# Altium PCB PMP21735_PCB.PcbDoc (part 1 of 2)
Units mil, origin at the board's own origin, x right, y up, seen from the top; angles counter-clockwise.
Board outline 1970 x 1570 mil, 4 copper layers (Top Layer, Signal Layer 1, Signal Layer 2, Bottom Layer), stack 61.6 mil thick; 74 components, 39 nets, 158 pads, 32 vias.
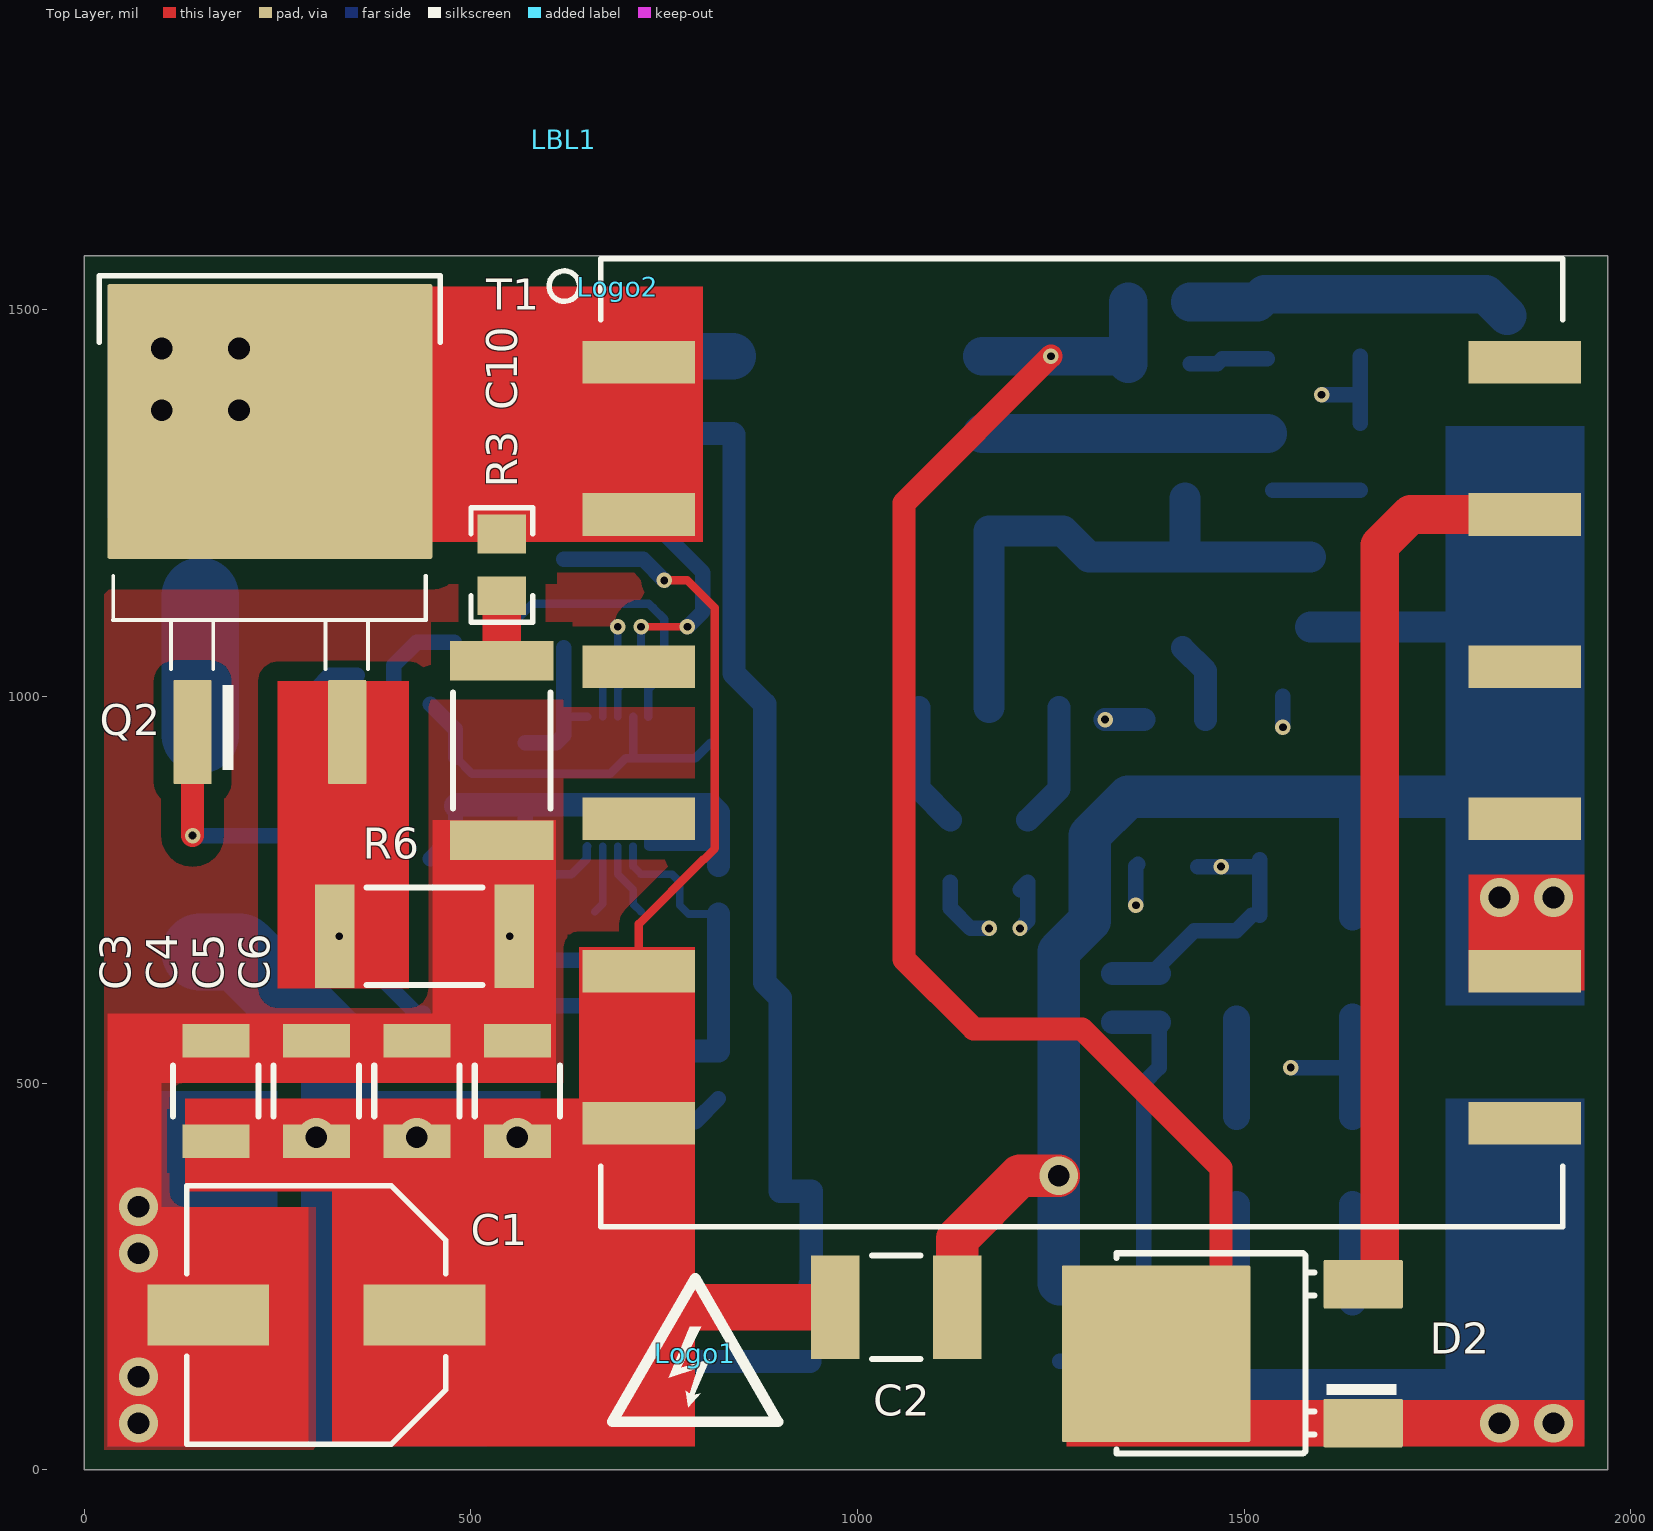
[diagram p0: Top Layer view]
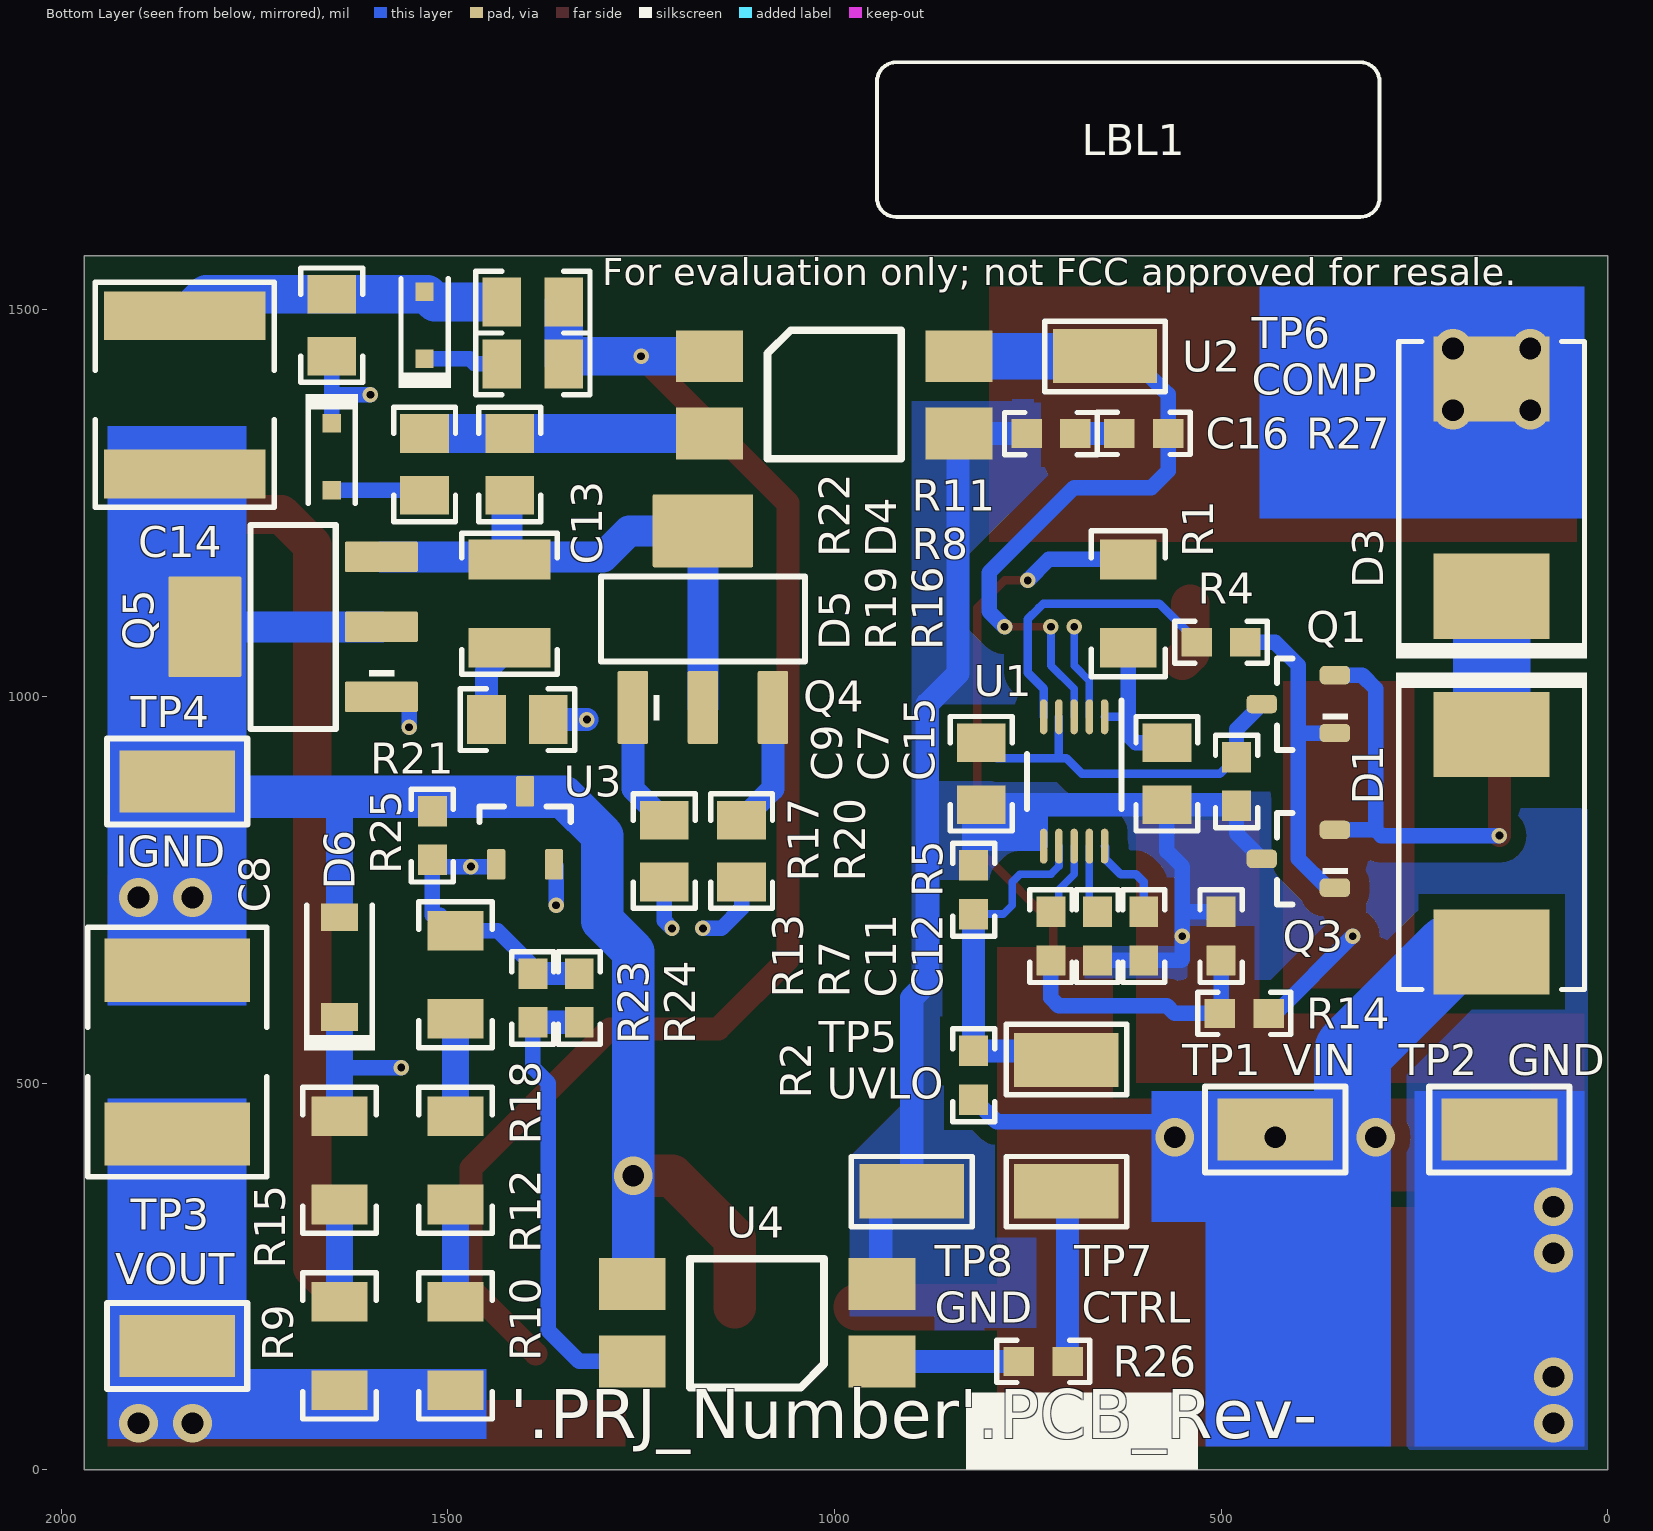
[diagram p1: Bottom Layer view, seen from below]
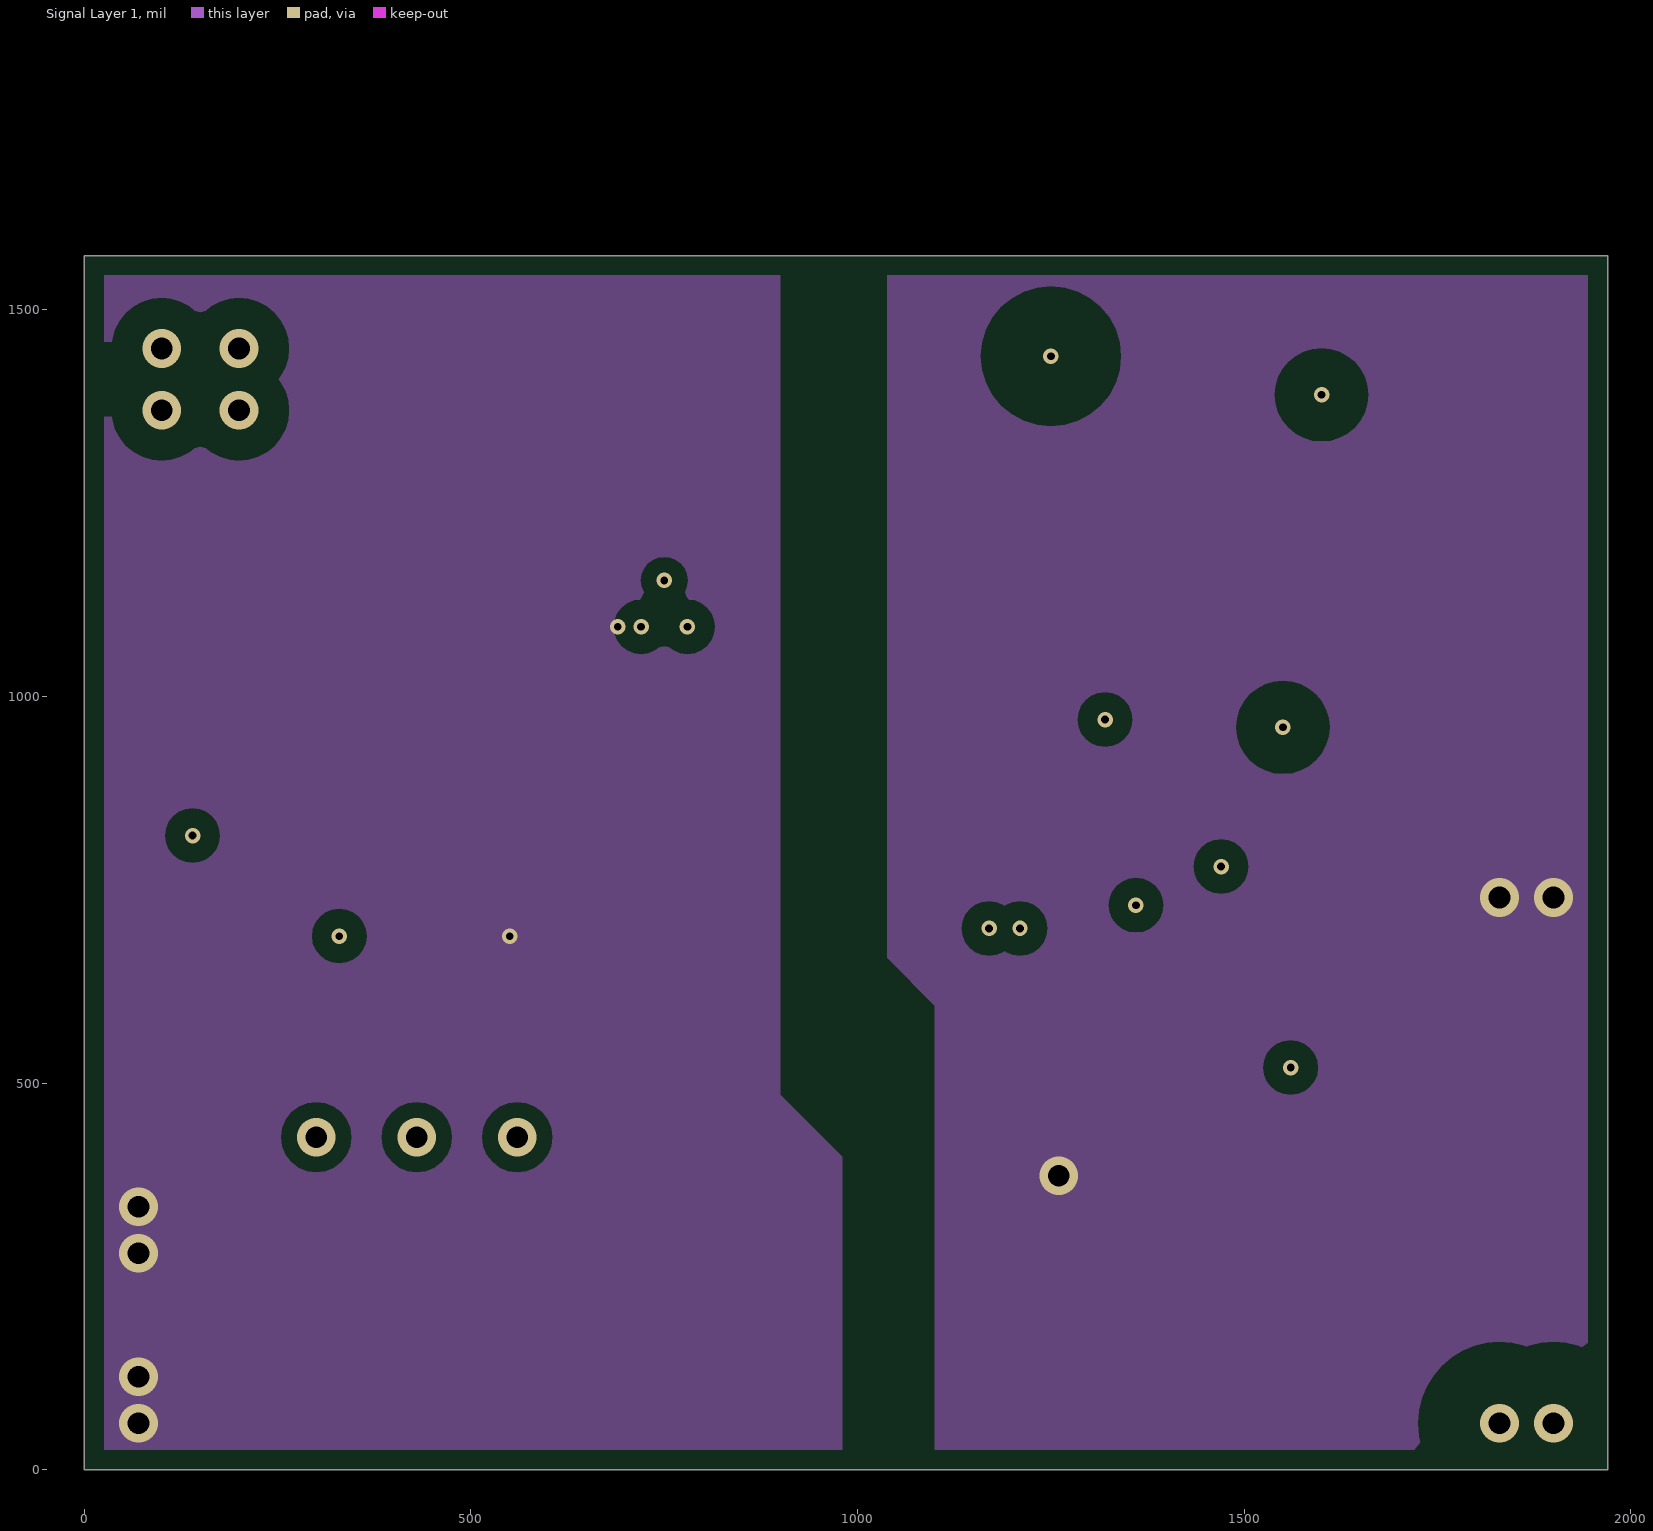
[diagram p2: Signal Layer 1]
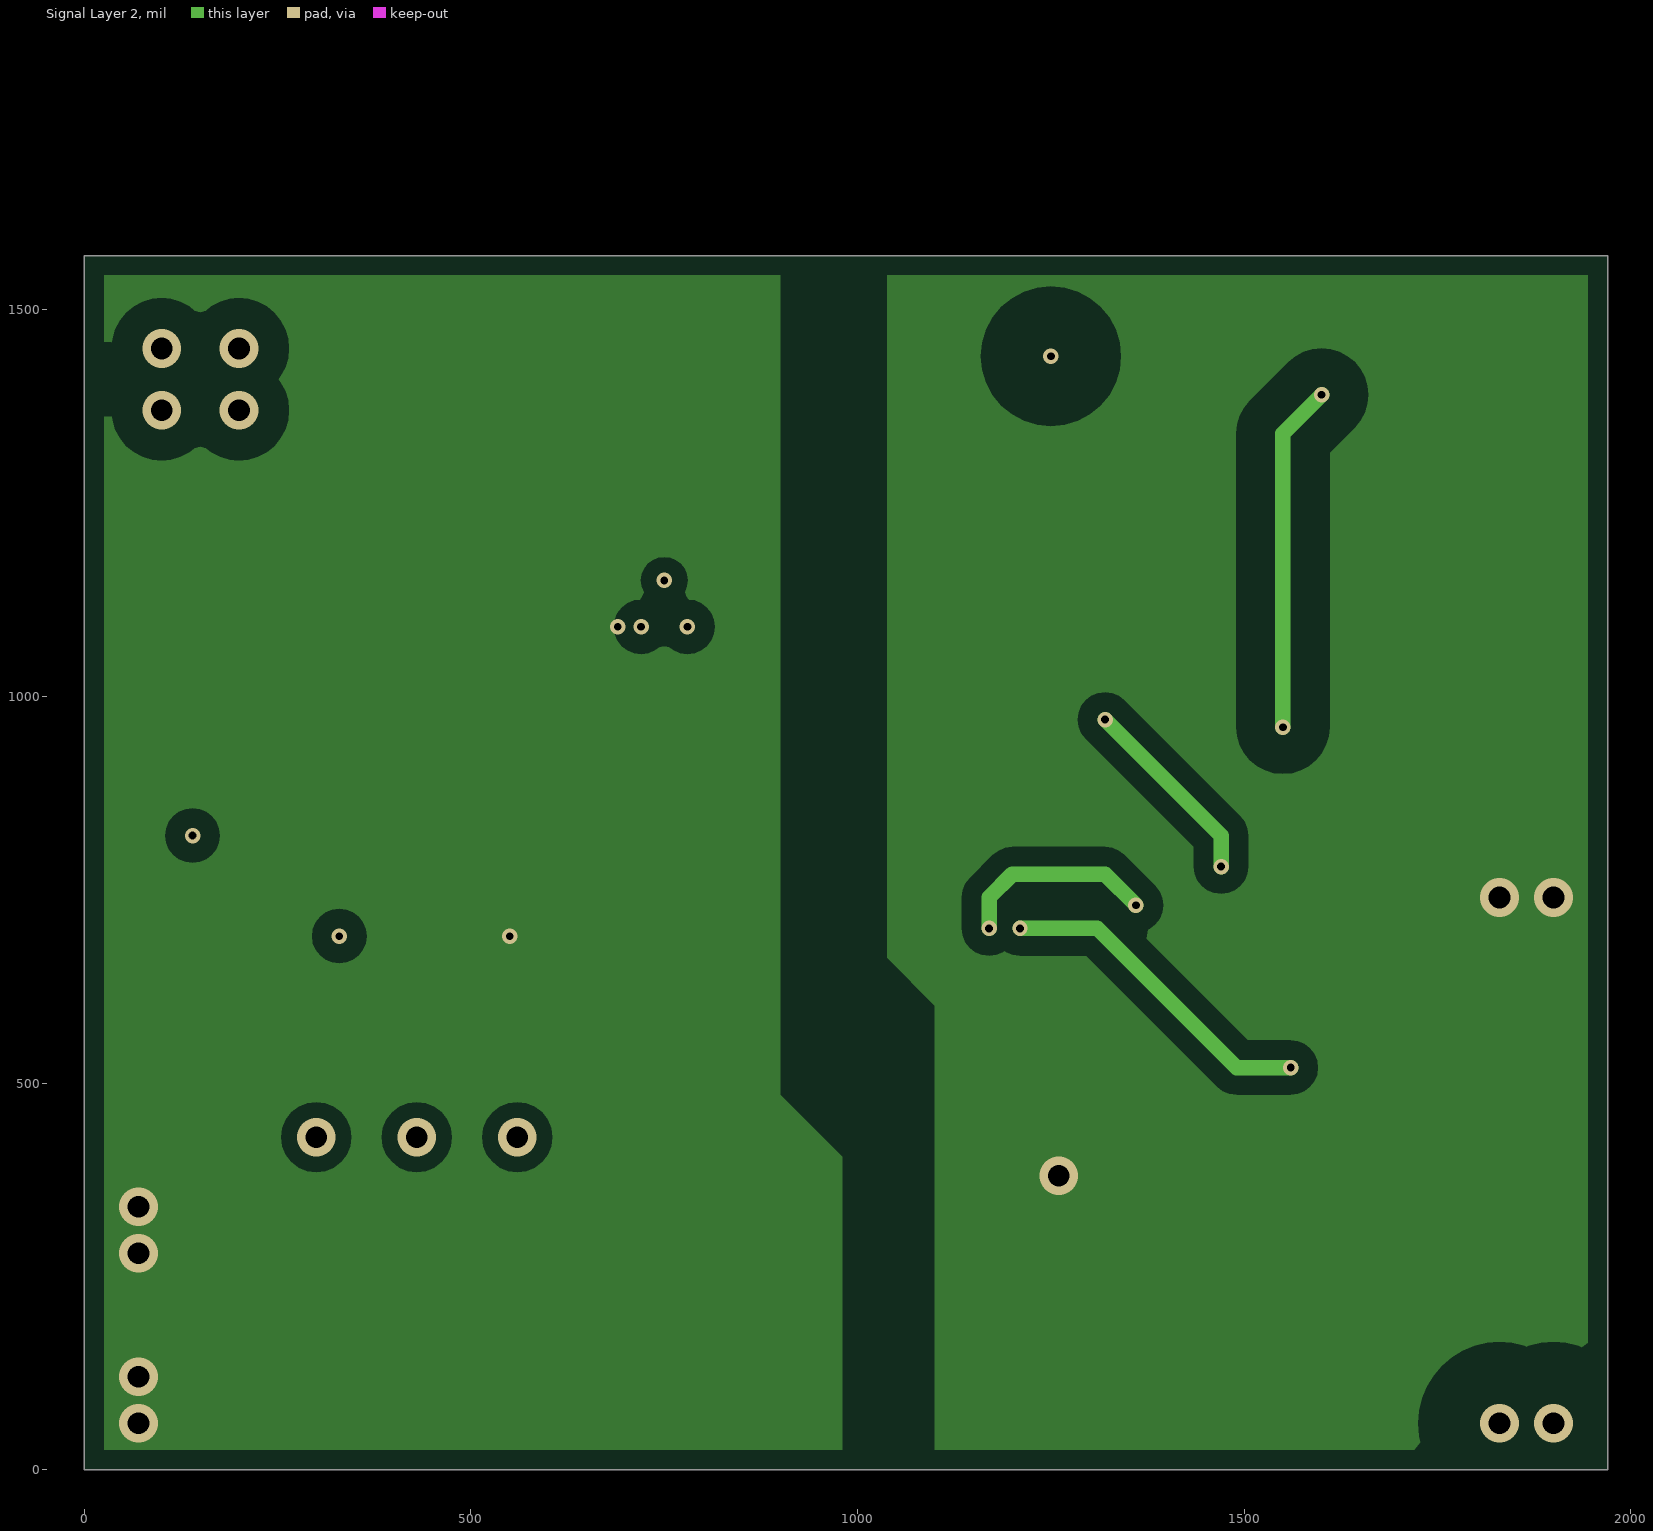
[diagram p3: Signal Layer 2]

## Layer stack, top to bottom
Top Solder: solder mask 0.4, Solder Resist, Dk 3.5
Top Layer: signal copper 1.4
Dielectric 1: prepreg 8, FR-4, Dk 4.2
Signal Layer 1: signal copper 1.4
Dielectric 2: core 40, FR-4, Dk 4.2
Signal Layer 2: signal copper 1.4
Dielectric 3: prepreg 8, FR-4, Dk 4.2
Bottom Layer: signal copper 1.4
Bottom Solder: solder mask 0.4, Solder Resist, Dk 3.5

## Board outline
0,0 1970,0 1970,1570 0,1570

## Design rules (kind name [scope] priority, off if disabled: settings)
AcuteAngle [All] p1: minimum=4.50000000000000E+0001 checktracksonly=FALSE
AssemblyTestPointUsage [All] p1: valid=2
BoardOutlineClearance BoardOutlineClearance_MountingHoles [OnCopper and InComponentClass('Mounting Holes')] p1: gap=40 ignorepadtopadclearanceinfootprint=FALSE
BoardOutlineClearance BoardOutlineClearance_Poly [OnCopper and IsPoly] p2: gap=25 ignorepadtopadclearanceinfootprint=FALSE
BoardOutlineClearance [OnCopper and Not InComponentClass('Logo') and not InComponentClass('FiducialMark') and not InRegion(1000,500,4000,800) and not InPoly] p3: gap=25 ignorepadtopadclearanceinfootprint=FALSE
Clearance Clearance_VIN_NoNet [InNet('VIN') vs InNet('No Net')] p1: gap=10 ignorepadtopadclearanceinfootprint=TRUE
Clearance Clearance_VIN_BP [InNet('VIN') vs InNet('BP')] p2: gap=8 ignorepadtopadclearanceinfootprint=TRUE
Clearance Clearance_VOUT_FB [InNet('VOUT') vs (InNet('FBT') OR InNet('RBT') OR InNet('VBZ'))] p3: gap=60 ignorepadtopadclearanceinfootprint=FALSE
Clearance Clearance_VOUT_SEC [InNet('VOUT') vs (InNet('SECSS') OR InNet('VK') OR InNet('VDK'))] p4: gap=20 ignorepadtopadclearanceinfootprint=FALSE
Clearance Clearance_VBP_VK [InNet('VBP') vs (InNet('VK') OR InNet('SECSS') OR InNet('VDK') OR InNet('VDA'))] p5: gap=20 ignorepadtopadclearanceinfootprint=FALSE
Clearance Clearance_VBP [InNet('VBP')] p6: gap=50 ignorepadtopadclearanceinfootprint=FALSE
Clearance Clearance_SWS [InNet('SWS')] p7: gap=80 ignorepadtopadclearanceinfootprint=TRUE
Clearance Clearance_VOUT [InNet('VOUT')] p8: gap=80 ignorepadtopadclearanceinfootprint=TRUE
Clearance Clearance_SWZ [InNet('SWZ')] p9: gap=40 ignorepadtopadclearanceinfootprint=TRUE
Clearance Clearance_SWP [InNet('SWP')] p10: gap=40 ignorepadtopadclearanceinfootprint=TRUE
Clearance Clearance_VIN [InNet('VIN')] p11: gap=20 ignorepadtopadclearanceinfootprint=TRUE
Clearance Clearance_Keepouts [((IsTrack Or IsArc) And Not InPoly) And IsFree and IsKeepOut vs ((IsTrack Or IsArc) And Not InPoly) And IsFree and IsKeepOut] p12: gap=0 ignorepadtopadclearanceinfootprint=FALSE
Clearance Clearance_Poly [InPolygon] p13: gap=25 ignorepadtopadclearanceinfootprint=FALSE except(0: Arc-Hole Track-Hole SMDPad-Hole THPad-Hole Via-Hole Fill-Hole Poly-Hole Region-Hole Text-Hole)
Clearance Clearance_FiducialMark [IsKeepOut and InComponentClass('FiducialMark') vs IsPad and InComponentClass('FiducialMark')] p14: gap=0 ignorepadtopadclearanceinfootprint=FALSE
Clearance [All] p15: gap=7.87 ignorepadtopadclearanceinfootprint=FALSE except(0: Arc-Hole Track-Hole SMDPad-Hole THPad-Hole Via-Hole Fill-Hole Poly-Hole Region-Hole Text-Hole)
ComponentClearance ComponentClearance_MountingHoles_FiducialMarks [InComponentClass('Mounting Holes') vs InComponentClass('FiducialMark')] p1: gap=50 collisioncheckmode=3 verticalgap=10 showdistances=FALSE
ComponentClearance ComponentClearance_Shunt [InComponentClass('Header') vs InComponentClass('Shunt')] p2: gap=0 collisioncheckmode=3 verticalgap=0 showdistances=FALSE
ComponentClearance ComponentClearance_Logo [InComponentClass('Logo')] p3: gap=50 collisioncheckmode=3 verticalgap=10 showdistances=FALSE
ComponentClearance ComponentClearance_ScrewToNut [(HasFootprint('NY PMS 440 0025 PH')) vs (HasFootprint('Keystone_1902C'))] p4: gap=5 collisioncheckmode=3 verticalgap=10 showdistances=FALSE
ComponentClearance ComponentClearance_MountingHoles [InComponentClass('Mounting Holes')] p5: gap=250 collisioncheckmode=3 verticalgap=100000 showdistances=FALSE
ComponentClearance ComponentClearance_SmallPassives [HasFootprint('0201*') or HasFootprint('0402*') or HasFootprint('0508') or HasFootprint('0603*') or HasFootprint('0612') or HasFootprint('0805*') or HasFootprint('0815*') or HasFootprint('0830*') or HasFootprint('1206*') or HasFootprint('1210*') or HasFootprint('1808*') or HasFootprint('1812*') or HasFootprint('1825*') or HasFootprint('2010*') or HasFootprint('2220*') or HasFootprint('2225*') or HasFootprint('2512*') or HasFootprint('2728*') or HasFootprint('3518*') vs HasFootprint('0201*') or HasFootprint('0402*') or HasFootprint('0508') or HasFootprint('0603*') or HasFootprint('0612') or HasFootprint('0805*') or HasFootprint('0815*') or HasFootprint('0830*') or HasFootprint('1206*') or HasFootprint('1210*') or HasFootprint('1808*') or HasFootprint('1812*') or HasFootprint('1825*') or HasFootprint('2010*') or HasFootprint('2220*') or HasFootprint('2225*') or HasFootprint('2512*') or HasFootprint('2728*') or HasFootprint('3518*')] p6: gap=14.96 collisioncheckmode=3 verticalgap=10 showdistances=FALSE
ComponentClearance ComponentClearance_THtoSMT [IsThruComponent vs IsSMTComponent] p7: gap=40 collisioncheckmode=3 verticalgap=30 showdistances=FALSE
ComponentClearance ComponentClearance_THtoTH [IsThruComponent vs IsThruComponent] p8: gap=30 collisioncheckmode=3 verticalgap=30 showdistances=FALSE
ComponentClearance [All] p9: gap=30 collisioncheckmode=3 verticalgap=10 showdistances=FALSE
DiffPairsRouting [All] p1: maxlimit=100 minlimit=10 mostfreqgap=10 toplayer_minwidth=15 toplayer_maxwidth=15 toplayer_prefwidth=15 midlayer1_minwidth=15 midlayer1_maxwidth=15 midlayer1_prefwidth=15 midlayer2_minwidth=15 midlayer2_maxwidth=15 midlayer2_prefwidth=15 bottomlayer_minwidth=15 bottomlayer_maxwidth=15 bottomlayer_prefwidth=15 maxuncoupledlength=1000
FabricationTestPointUsage TestPointUsage [All] p1: valid=2 allowmultiple=FALSE
FabricationTestpoint Testpoint [All] p1: side=3 testpointundercomponent=TRUE minsize=40 maxsize=100 preferedsize=60 minholesize=0 maxholesize=40 preferedholesize=32 testpointgrid=1 allowsidetop=TRUE allowsidebottom=TRUE usegrid=TRUE gridtolerance=0.01
FanoutControl Fanout_LCC [IsLCC] p1: bgadir=Out bgaviamode=Centered fanoutstyle=Auto fanoutdirection=Alternating viagrid=1 // Fanout_LCC (Default Rule)
FanoutControl Fanout_BGA [IsBGA] p2: bgadir=Out bgaviamode=Centered fanoutstyle=Auto fanoutdirection=Alternating viagrid=1 // Fanout_BGA (Default Rule)
FanoutControl Fanout_Default [All] p4: bgadir=Out bgaviamode=Centered fanoutstyle=Auto fanoutdirection=Alternating viagrid=1 // Fanout_Default (Default Rule)
FanoutControl Fanout_Small [(CompPinCount < 5)] p5: bgadir=Out bgaviamode=Centered fanoutstyle=Auto fanoutdirection=OutThenIn viagrid=1 // Fanout_Small (Default Rule)
HoleSize [All] p1: absolutevalues=TRUE maxlimit=251 minlimit=7.87 maxpercent=80.000 minpercent=20.000
MinimumAnnularRing MinimumAnnularRing_ThermalPadVias [IsVia and InAnyComponent] p1: minimumring=5.91
MinimumAnnularRing [All] p2: minimumring=5
MinimumSolderMaskSliver MinimumSolderMaskSliver_Logo [InComponentClass('Logo') vs InComponentClass('Logo')] p1: minsoldermaskwidth=0.7
MinimumSolderMaskSliver [All] p2: minsoldermaskwidth=3.94
PlaneConnect [All] p1: planeconnectstyle=Direct reliefexpansion=10 reliefentries=4 reliefconductorwidth=10 reliefairgap=10
PolygonConnect [All] p1: connectstyle=Direct reliefconductorwidth=10 reliefentries=4 polygonreliefangle="90 Angle" airgapwidth=10
RoutingVias ThermalPadVias [IsVia and InAnyComponent] p1: holewidth=7.87 width=19.68 viastyle="Through Hole" minholewidth=7.87 minwidth=19.68 maxholewidth=12.99 maxwidth=23.62
RoutingVias [All] p2: holewidth=16 width=34 viastyle="Through Hole" minholewidth=7.87 minwidth=20 maxholewidth=40 maxwidth=65
SilkToBoardRegionClearance [Not ((IsComment or IsDesignator) And (Hide <> 'False')) and not InRegion(1000,500,4000,800)] p1:
SilkToSilkClearance SilkToSilkClearance_Pb-FreeLogo [(HasFootprint('Pb-Free_Overlay_Medium') OR HasFootprint('Pb-Free_Overlay_Small')) vs (HasFootprint('Pb-Free_Overlay_Medium') OR HasFootprint('Pb-Free_Overlay_Small'))] p1: silktosilkclearance=0
SilkToSilkClearance [All] p2: silktosilkclearance=4
SilkToSolderMaskClearance SilkToComponentPadClearance [(IsPad or IsFill or IsRegion) and InAnycomponent] p1: minsilkscreentomaskgap=5 clearancetoexposedcopper=TRUE
SilkToSolderMaskClearance "Silk to Solder Mask Opening" [All] p2: minsilkscreentomaskgap=4 clearancetoexposedcopper=FALSE
SolderMaskExpansion [All] p1: expansion=1.97
Width [All] p1: maxlimit=100 minlimit=6 preferedwidth=10 checkconnectedcopper=TRUE
15 further rules are at their usual default settings.

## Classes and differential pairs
component class PMP21735_Sh2: LBL1 Logo1 Logo2 ZZ1 ZZ2 ZZ3 ZZ4
component class AssemblyNote: ZZ1 ZZ2 ZZ3 ZZ4
component class Label: LBL1

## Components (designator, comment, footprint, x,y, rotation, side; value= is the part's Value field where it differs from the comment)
C1 "EEE-FK1H101P" SM_RADIAL_F 300,200 r180 top value=100uF
C2 "1812HC222KAT1A" 1812_254 1050,210 r180 top value=2200pF
C3 "C1210C475K5RACAUTO" 1210_280 170,490 r90 top value=4.7uF
C4 "C1210C475K5RACAUTO" 1210_280 300,490 r90 top value=4.7uF
C5 "C1210C475K5RACAUTO" 1210_280 430,490 r90 top value=4.7uF
C6 "C1210C475K5RACAUTO" 1210_280 560,490 r90 top value=4.7uF
C7 "GRM21BR71H105KA12L" 0805_HV 570,900 r270 bottom value=1uF
C8 "C2220C105MCR2C7186" KPS_600x500x500 1850,540 r90 bottom value=1uF
C9 "GRM21BZ71E106KE15L" 0805_HV 810,900 r270 bottom value=10uF
C10 "GRM21AR72E222KW01D" 0805_HV 540,1170 r270 top value=2200pF
C11 "C0603C104K5RACAUTO" 0603 600,690 r270 bottom value=0.1uF
C12 "CGA3E2NP01H101J080AA" 0603 500,690 r90 bottom value=100pF
C13 "C1210W104KCRACTU" 1210_230 1420,1120 r270 bottom value=0.1uF
C14 "VJ2220Y224KBEAT4X" 2220_220 1840,1390 r270 bottom value=0.22uF
C15 "GRM188R71E105KA12D" 0603 480,890 r270 bottom value=1uF
C16 "GCM188R71E224KA55D" 0603 720,1340 r0 bottom value=0.22uF
D1 "5.0SMDJ130A" SMC 150,810 r270 bottom value=130V
D2 "C4D02120E" DPAK 1520,150 r180 top value=1200V
D3 "ES3D-E3/57T" SMC 150,1270 r90 bottom value=200V
D4 "1N4148WX-TP" SOD-323 1530,1480 r90 bottom value=75V
D5 "1N4148WX-TP" SOD-323 1650,1310 r270 bottom value=75V
D6 "MMSZ5242B-7-F" SOD-123 1640,650 r90 bottom value=12V
LBL1 "THT-14-423-10" Label_650x200 620,1720 r0 top
Logo1 "DANGER HIGH VOLTAGE" IEC_HighVoltage_Small 790,150 r0 top
Logo2 "FCC disclaimer" FCC_disclaimer 690,1530 r0 top
Q1 "FMMT618TA" SOT-23 400,990 r0 bottom value="20 V"
Q2 "SQM90142E_GE3" DDPAK 240,1200 r90 top value=200V
Q3 "FMMT718TA" SOT-23 400,790 r0 bottom value="20 V"
Q4 "PBHV8560ZX" SOT-223 1170,1100 r90 bottom value="600 V"
Q5 "PBHV9560ZX" SOT-223 1700,1090 r0 bottom value="600 V"
R1 "CRCW12063R30JNEA" 1206 620,1120 r90 bottom value=3.3
R2 "CRCW060321K0FKEA" 0603 820,510 r270 bottom value=21.0k
R3 "CRCW25124R70JNEG" 2512 540,930 r90 top value=4.7
R4 "CRCW06033R30JNEA" 0603 500,1070 r180 bottom value=3.3
R5 "CRCW06033K48FKEA" 0603 820,750 r270 bottom value=3.48k
R6 "CSNL2512FT4L00" 2512 440,690 r180 top value=0.004
R7 "CRCW0603158KFKEA" 0603 660,690 r90 bottom value=158k
R8 "CRCW08052K00JNEA" 0805_HV 1390,1430 r0 bottom value=2.0k
R9 "CRCW12061M00JNEA" 1206 1640,160 r270 bottom value=1.0Meg
R10 "CRCW1206332KFKEA" 1206 1490,160 r270 bottom value=332k
R11 "CRCW08051M00JNEA" 0805_HV 1390,1510 r180 bottom value=1.0Meg
R12 "CRCW1206332KFKEA" 1206 1490,400 r270 bottom value=332k
R13 "CRCW06036K04FKEA" 0603 720,690 r270 bottom value=6.04k
R14 "CRCW06031K00FKEA" 0603 470,590 r180 bottom value=1.00k
R15 "CRCW12061M00JNEA" 1206 1640,400 r270 bottom value=1.0Meg
R16 "CRCW08052K00JNEA" 0805_HV 1420,1300 r270 bottom value=2.0k
R17 "CRCW08052K00JNEA" 0805_HV 1220,800 r90 bottom value=2.0k
R18 "CRCW1206332KFKEA" 1206 1490,640 r270 bottom value=332k
R19 "CRCW080551K0JNEA" 0805_HV 1530,1300 r90 bottom value=51k
R20 "CRCW08054K70JNEA" 0805_HV 1120,800 r90 bottom value=4.7k
R21 "CRCW08051M00JNEA" 0805_HV 1410,970 r0 bottom value=1.0Meg
R22 "CRCW080551K0JNEA" 0805_HV 1650,1480 r270 bottom value=51k
R23 "RG1608P-3651-B-T5" 0603 1390,610 r90 bottom value=3.65k
R24 "CRCW060326K1FKEA" 0603 1330,610 r90 bottom value=26.1k
R25 "CRCW060321K0FKEA" 0603 1520,820 r270 bottom value=21.0k
R26 "CRCW06032K00JNEA" 0603 730,140 r180 bottom value=2.0k
R27 "CRCW060322R0JNEA" 0603 600,1340 r180 bottom value=22
T1 "PM2522NL" EFD30 1290,940 r0 top value=5uH
TP1 "VIN" Keystone_5019 430,440 r0 bottom
TP2 "GND" Keystone_5019 140,440 r0 bottom
TP3 "VOUT" Keystone_5019 1850,160 r180 bottom
TP4 "IGND" Keystone_5019 1850,890 r180 bottom
TP5 "UVLO" Testpoint_Keystone_Miniature 700,530 r0 bottom
TP6 "COMP" Testpoint_Keystone_Miniature 650,1440 r180 bottom
TP7 "CTRL" Testpoint_Keystone_Miniature 700,360 r180 bottom
TP8 "GND" Testpoint_Keystone_Miniature 900,360 r180 bottom
U1 "LM5022QDGSRQ1" DGS0010A_L 690,890 r270 bottom
U2 "PS2501L-1-F3-H-A" PS2501L 1000,1390 r180 bottom
U3 "LMV431AIMFX/NOPB" DBZ0003A_N 1400,830 r90 bottom
U4 "PS2501L-1-F3-H-A" PS2501L 1100,190 r0 bottom
ZZ1 "This Assembly Note is for PCB labels only" AssemblyNoteLabel 185,2338 r0 top
ZZ2 "These assemblies are ESD sensitive, ESD precautions shall be observed." AssemblyNote 185,2229.11 r0 top
ZZ3 "These assemblies must be clean and free from flux and all contaminants. Use of no clean flux is not acceptable." AssemblyNote 185,2140.56 r0 top
ZZ4 "These assemblies must comply with workmanship standards IPC-A-610 Class 2, unless otherwise specified." AssemblyNote 185,2052 r0 top

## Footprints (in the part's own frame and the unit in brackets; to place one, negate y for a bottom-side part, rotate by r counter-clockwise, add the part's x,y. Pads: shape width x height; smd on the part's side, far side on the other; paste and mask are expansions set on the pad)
0603 [mm] "0603 from SM-752 data"
  rect 1x0.95 smd: 1(-0.8,0) 2(0.8,0)
  silkscreen extent -1.52,-0.69 1.52,0.69, body extent -0.87,-0.47 0.87,0.47, height 1
0805_HV [mil] "0805 with 30mil clearance between pads"
  rect 50x63 smd: 1(-40,0) 2(40,0)
  silkscreen extent -74,-40 74,40, body extent -43,-29 43,29, height 57
1206 [mm] "1206 from SM-752 data"
  rect 1.3x1.85 smd: 1(-1.45,0) 2(1.45,0)
  silkscreen extent -2.4,-1.21 2.4,1.21, body extent -1.7,-0.9 1.7,0.9, height 1.35
1210_230 [mm] "1210"
  rect 1.3x2.7 smd: 1(-1.45,0) 2(1.45,0)
  silkscreen extent -2.32,-1.57 2.32,1.57, body extent -1.7,-1.35 1.7,1.35, height 2.3
1210_280 [mm] "SMD, 2-Leads, Body 3.6x2.8mm, Height 2.8mm"
  rect 1.1x2.2 smd: 1(-1.65,0) 2(1.65,0)
  silkscreen extent -0.84,-1.4 0.84,1.4, body extent -1.8,-1.4 1.8,1.4, height 2.8
1812_254 [mm] "SMD, 2-Leads, Body 4.8x3.4mm"
  rect 1.6x3.4 smd: 1(-2,0) 2(2,0)
  silkscreen extent -0.8,-1.7 0.8,1.7, body extent -2.4,-1.7 2.4,1.7, height 2.54
2220_220 [mm] "Chip Capacitor, Body 5.7x5.0mm, IPC Medium Density"
  rect 1.6x5.3 smd: 1(-2.6,0) 2(2.6,0)
  silkscreen extent -3.69,-2.94 3.69,2.94, body extent -2.95,-2.62 2.95,2.62, height 2.2
2512 [mm] "Chip Resistor, Body 6.3x3.2mm, IPC Medium Density"
  rect 1.3x3.4 smd: 1(-2.95,0) 2(2.95,0)
  silkscreen extent -1.9,-1.6 1.9,1.6, body extent -3.22,-1.67 3.22,1.67, height 0.71
AssemblyNote [mil] "Assembly Note"
AssemblyNoteLabel [mil] "Assembly Note for PCB Labels"
DBZ0003A_N [mm] "SOT23, 3-Leads, Body 2.9x1.3mm, Pitch 0.95mm, Lead Span 2.4mm, IPC Medium Density"
  rrect17% 1x0.6 smd: 1(-1.2,0.95) 2(-1.2,-0.95) 3(1.2,0)
  silkscreen extent 0.2,-1.5 0.7,1.5, body extent -1.26,-1.46 1.26,1.46, height 0.98
DDPAK [mil] "D2-PAK, 3-Pads, Body 9.7x10.4mm (max), TO-263AB, using Vishay Silionix recommended pad sizes"
  rrect8% 135x49.49 smd: 1(-246.06,100) 3(-246.06,-100)
  rrect1% 355x420 smd paste-181.1: 4(155.51,0)
  silkscreen extent -295,-220 344,220, body extent -295,-202 324,202, height 180
DGS0010A_L [mm] "TSSOP, 10-Leads, Body 3x3mm, Pitch 0.5mm, IPC High Density"
  oval 1.15x0.25 smd: 1(-2.125,1) 2(-2.125,0.5) 3(-2.125,0) 4(-2.125,-0.5) 5(-2.125,-1) 6(2.125,-1) 7(2.125,-0.5) 8(2.125,0) 9(2.125,0.5) 10(2.125,1)
  silkscreen extent -2.65,-1.55 0.9,1.55, body extent -2.45,-1.5 2.45,1.5, height 0.96
DPAK [mm] "D-PAK, 3-Pads, Body 6.22x6.73mm (max), TO-252AA using nominal STEP model"
  rrect6% 2.6x1.6 smd: 1(-3.4,2.28) 3(-3.4,-2.28)
  rrect2% 6.2x5.8 smd paste-2.9: 4(3.4,0)
  silkscreen extent -4.5,-3.3 4.7,3.28, body extent -3.86,-3.29 5.84,3.29, height 2.48
EFD30 [mm] "Recommended land pattern for Pulse EFD transformer"
  rect 3.7x1.4 smd: 1(-14.55,12.5) 2(-14.55,7.5) 3(-14.55,2.5) 4(-14.55,-2.5) 5(-14.55,-7.5) 6(-14.55,-12.5) 7(14.55,-12.5) 8(14.55,-7.5) 9(14.55,-2.5) 10(14.55,2.5) 11(14.55,7.5) 12(14.55,12.5)
  silkscreen extent -17.5,-15.9 15.8,15.9, body extent -15.8,-15.9 15.8,15.9, height 14.8
FCC_disclaimer [mil]
IEC_HighVoltage_Small [mil]
  silkscreen extent -107,-88 107,97
Keystone_5019 [mm] "Test Point, Miniature, SMT"
  rect 3.8x2.03 smd: 1(0,0)
  silkscreen extent -2.31,-1.42 2.31,1.42, body extent -1.91,-1.02 1.9,1.02, height 2.29
KPS_600x500x500 [mm] "SMD, 2-Leads, Body 6x5mm"
  rect 2.08x4.78 smd: 1(-2.69,0) 2(2.69,0)
  silkscreen extent -4.1,-2.94 4.1,2.94, body extent -3.25,-2.75 3.25,2.75, height 5.5
Label_650x200 [mil] "Thermal Transfer Label"
  round 1 on Mech13: 0(0,0)
  body extent -325,-100 325,100, height 1
PS2501L [mm] "NEC optocoupler"
  rect 2.2x1.7 smd: 1(-4.1,1.27) 2(-4.1,-1.27) 3(4.1,-1.27) 4(4.1,1.27)
  silkscreen extent -2.2,-2.1 2.2,2.12, body extent -5,-2.29 5,2.29, height 3.87
SM_RADIAL_F [mm] "8 x 10.2mm:  Panasonic F"
  rect 4x2 smd: 1(-3.55,0) 2(3.55,0)
  silkscreen extent -4.25,-4.25 4.25,4.25, body extent -4.25,-4.25 4.25,4.25, height 10.5
SMC [mil] "Molded Diode, 2-Leads, Body 6.9x5.8mm, IPC Medium Density, based on OnSemi component dimensions and land patterns"
  rect 110x150 smd: 1(-140.49,0) 2(140.49,0)
  silkscreen extent -221,-123 189,124, body extent -156,-116 156,116, height 91
SOD-123 [mm] "On Semi recommended land pattern"
  rect 0.915x1.22 smd: 1(-1.637,0) 2(1.637,0)
  silkscreen extent -2.74,-1.17 2.03,1.17, body extent -1.93,-0.9 1.93,0.9, height 1.35
SOD-323 [mm] "NXP recommended land pattern"
  rect 0.6x0.6 smd paste-0.05: 1(-1.1,0) 2(1.1,0)
  silkscreen extent -2.06,-0.86 1.53,0.86, body extent -1.3,-0.67 1.3,0.68, height 1.1
SOT-23 [mm] "SOT23, 3-Leads, Body 2.9x1.3mm, Pitch 0.95mm, Lead Span 2.5mm, IPC Medium Density"
  rrect50% 1x0.6 smd: 1(-1.2,0.95) 2(-1.2,-0.95) 3(1.2,0)
  silkscreen extent -1.62,-1.5 0.7,1.5, body extent -1.16,-1.45 1.21,1.45, height 1
SOT-223 [mm] "SOT223/SC73, 4-Leads, Body 6.5x3.5mm, Pitch 2.3mm, Lead Span 7mm, IPC Medium Density"
  rrect10% 2.4x1 smd: 1(-2.9,2.3) 2(-2.9,0) 3(-2.9,-2.3)
  rrect4% 2.4x3.3 smd: 4(2.9,0)
  silkscreen extent -3.32,-3.35 1.4,3.35, body extent -3.5,-3.25 3.5,3.25, height 1.62
Testpoint_Keystone_Miniature [mil] "Miniature SMT test point"
  rect 135x70 smd: 1(0,0)
  silkscreen extent -78,-46 78,45, body extent -52,-20 52,20, height 61

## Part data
C1: library part CMP-0011177-2, "CAP, AL, 100 uF, 50 V, +/- 20%, 0.34 ohm, AEC-Q200 Grade 2, SMD", Cap_Case=F, Manufacturer=Panasonic, Supplier Part Number 1=PCE3809CT-ND, Tolerance_%=20%, Value1="0.34 ohm", Value2=50V, ValueDisplayed=100uF
C2: library part CMP-0009296-2, "CAP, CERM, 2200 pF, 3000 V, +/- 10%, X7R, 1812", Cap_Case=1812, Manufacturer=AVX, Supplier Part Number 1=478-4733-1-ND, TempCo=X7R, Tolerance_%=10%, Value1=Unknown, Value2=3000V, ValueDisplayed=2200pF
C3 C4 C5 C6: library part CMP-0079604-1, "CAP, CERM, 4.7 µF, 50 V,+/- 10%, X7R, AEC-Q200 Grade 1, 1210", Cap_Case=1210, Manufacturer=Kemet, Supplier Part Number 1=399-7049-1-ND, TempCo=X7R, Tolerance_%=10%, Value2=50V, ValueDisplayed=4.7µF
C7: library part CMP-0008350-2, "CAP, CERM, 1 uF, 50 V, +/- 10%, X7R, 0805", Cap_Case=0805, Manufacturer=MuRata, Supplier Part Number 1=490-4736-1-ND, TempCo=X7R, Tolerance_%=10%, Value1=Unknown, Value2=50V, ValueDisplayed=1uF
C8: library part CMP-0009328-2, "CAP, CERM, 1 uF, 500 V, +/- 20%, X7R, AEC-Q200 Grade 1, 6x5mm", Cap_Case=2220, Manufacturer=Kemet, Supplier Part Number 1=399-9630-1-ND, TempCo=X7R, Tolerance_%=20%, Value1=Unknown, Value2=500V, ValueDisplayed=1uF
C9: library part CMP-0008378-2, "CAP, CERM, 10 uF, 25 V, +/- 10%, X7R, 0805", Cap_Case=0805, Manufacturer=MuRata, Supplier Part Number 1=81-GRM21BZ71E106KE5L, TempCo=X7R, Tolerance_%=10%, Value1=Unknown, Value2=25V, ValueDisplayed=10uF
C10: library part CMP-0008253-2, "CAP, CERM, 2200 pF, 250 V, +/- 10%, X7R, 0805", Cap_Case=0805, Manufacturer=MuRata, Supplier Part Number 1=490-3529-1-ND, TempCo=X7R, Tolerance_%=10%, Value1=Unknown, Value2=250V, ValueDisplayed=2200pF
C11: library part CMP-0079602-1, "CAP, CERM, 0.1 µF, 50 V,+/- 10%, X7R, AEC-Q200 Grade 1, 0603", Cap_Case=0603, Manufacturer=Kemet, Supplier Part Number 1=399-6856-1-ND, TempCo=X7R, Tolerance_%=10%, Value2=50V, ValueDisplayed=0.1µF
C12: library part CMP-0007075-4, "CAP, CERM, 100 pF, 50 V, +/- 5%, C0G/NP0, AEC-Q200 Grade 0, 0603", Cap_Case=0603, Manufacturer=TDK, Supplier Part Number 1=445-12386-1-ND, TempCo=C0G/NP0, Tolerance_%=5%, Value1=Unknown, Value2=50V, ValueDisplayed=100pF
C13: library part CMP-0009094-1, "CAP, CERM, 0.1 uF, 500 V, +/- 10%, X7R, 1210", Cap_Case=1210, Manufacturer=Kemet, Supplier Part Number 1=399-6508-1-ND, TempCo=X7R, Tolerance_%=10%, Value1=Unknown, Value2=500V, ValueDisplayed=0.1uF
C14: library part CMP-0009579-2, "CAP, CERM, 0.22 uF, 500 V, +/- 10%, X7R, 2220", Cap_Case=2220, Manufacturer=Vishay-Vitramon, Supplier Part Number 1=720-1093-1-ND, TempCo=X7R, Tolerance_%=10%, Value1=Unknown, Value2=500V, ValueDisplayed=0.22uF
C15: library part CMP-0007405-4, "CAP, CERM, 1 uF, 25 V, +/- 10%, X7R, 0603", Cap_Case=0603, Manufacturer=MuRata, Supplier Part Number 1=490-5307-1-ND, TempCo=X7R, Tolerance_%=10%, Value1=Unknown, Value2=25V, ValueDisplayed=1uF
C16: library part CMP-0007140-4, "CAP, CERM, 0.22 uF, 25 V, +/- 10%, X7R, AEC-Q200 Grade 1, 0603", Cap_Case=0603, Manufacturer=MuRata, Supplier Part Number 1=490-4935-1-ND, TempCo=X7R, Tolerance_%=10%, Value1=Unknown, Value2=25V, ValueDisplayed=0.22uF
D1: library part CMP-0005706-2, "Diode, TVS, Uni, 130 V, 209 Vc, SMC", Manufacturer=Littelfuse, Power_W=6.5W, Supplier Part Number 1=5.0SMDJ130ACT-ND
D2: library part CMP-0076990-1, "Diode, Schottky, 1200 V, 10 A, DPAK", Manufacturer=Cree, Supplier Part Number 1=C4D02120E-ND, Value1=10A, Value2=1.8V
D3: library part CMP-0029041-1, "Diode, Ultrafast, 200 V, 3 A, SMC", Manufacturer=Vishay-Semiconductor, Supplier Part Number 1=ES3D-E3/57TGICT-ND, Value1=3A, Value2=0.9V
D4 D5: library part CMP-0082069-1, "Diode, Switching, 75 V, 0.15 A, SOD-323", Manufacturer="Micro Commercial Components", Supplier Part Number 1=1N4148WXTPMSCT-ND, Value1=0.15A, Value2=1V
D6: library part CMP-0005751-2, "Diode, Zener, 12 V, 500 mW, SOD-123", Manufacturer="Diodes Inc.", Power_W=500mW, Supplier Part Number 1=MMSZ5242B-FDICT-ND, Value1=0.5W
LBL1: library part CMP-0003625-1, "Thermal Transfer Printable Labels, 0.650\" W x 0.200\" H - 10,000 per roll", Manufacturer=Brady, Supplier Part Number 1=97C5133
Logo1: library part CMP-0074835-1, "IEC 61010-1 High Voltage Warning"
Logo2: library part CMP-0074847-1, "FCC_disclaimer"
Q1: library part CMP-0000494-2, "Transistor, NPN, 20 V, 2.5 A, AEC-Q101, SOT-23", Manufacturer="Diodes Inc.", Supplier Part Number 1=FMMT618CT-ND, Value1="2.5 A", Value2=450
Q2: library part CMP-0001092-3, "MOSFET, N-CH, 200 V, 65 A, DDPAK", Alternate Manufacturer=None, Manufacturer=Vishay-Siliconix, Supplier Part Number 1=SQM90142E_GE3CT-ND, Value2="85 nC"
Q3: library part CMP-0000330-2, "Transistor, PNP, 20 V, 1.5 A, SOT-23", Manufacturer="Diodes Inc.", Supplier Part Number 1=FMMT718CT-ND, Value1="1.5 A", Value2=6
Q4: library part CMP-0000450-2, "Transistor, NPN, 600 V, 0.5 A, SOT-223", Manufacturer=Nexperia, Supplier Part Number 1=1727-2369-1-ND, Value1="0.5 A", Value2=70
Q5: library part CMP-0000371-2, "Transistor, PNP, 600 V, 0.5 A, AEC-Q101, SOT-223", Manufacturer=Nexperia, Supplier Part Number 1=1727-2372-1-ND, Value1="0.5 A", Value2=70
R1: library part CMP-0018677-3, "RES, 3.3, 5%, 0.25 W, AEC-Q200 Grade 0, 1206", Manufacturer=Vishay-Dale, Power_W=250mW, Supplier Part Number 1=541-3.3ECT-ND, TempCo="200 ppm/C", Tolerance_%=5%, Value2=0.25W, Value_Code=3R30, ValueDisplayed=3.3
R2 R25: library part CMP-0022212-4, "RES, 21.0 k, 1%, 0.1 W, AEC-Q200 Grade 0, 0603", Manufacturer=Vishay-Dale, Power_W=100mW, Supplier Part Number 1=541-21.0KHCT-ND, TempCo="100 ppm/C", Tolerance_%=1%, Value2=0.1W, Value_Code=21k0, ValueDisplayed=21.0k
R3: library part CMP-0015974-3, "RES, 4.7, 5%, 1 W, AEC-Q200 Grade 0, 2512", Manufacturer=Vishay-Dale, Power_W=1W, Supplier Part Number 1=541-4.7XCT-ND, TempCo="200 ppm/C", Tolerance_%=5%, Value_Code=4R70, ValueDisplayed=4.7
R4: library part CMP-0025805-4, "RES, 3.3, 5%, 0.1 W, AEC-Q200 Grade 0, 0603", Manufacturer=Vishay-Dale, Power_W=100mW, Supplier Part Number 1=541-3.3GCT-ND, TempCo="200 ppm/C", Tolerance_%=5%, Value2=0.1W, Value_Code=3R30, ValueDisplayed=3.3
R5: library part CMP-0022377-4, "RES, 3.48 k, 1%, 0.1 W, AEC-Q200 Grade 0, 0603", Manufacturer=Vishay-Dale, Power_W=100mW, Supplier Part Number 1=541-3.48KHCT-ND, TempCo="100 ppm/C", Tolerance_%=1%, Value2=0.1W, Value_Code=3k48, ValueDisplayed=3.48k
R6: library part CMP-0015757-2, "RES, 0.004, 1%, 2 W, 2512", Manufacturer="Stackpole Electronics Inc", Power_W=2W, Supplier Part Number 1=CSNL2512FT4L00CT-ND, TempCo="50 ppm/C", Tolerance_%=1%, Value_Code=4L000, ValueDisplayed=0.004
R7: library part CMP-0022064-4, "RES, 158 k, 1%, 0.1 W, AEC-Q200 Grade 0, 0603", Manufacturer=Vishay-Dale, Power_W=100mW, Supplier Part Number 1=541-158KHCT-ND, TempCo="100 ppm/C", Tolerance_%=1%, Value2=0.1W, Value_Code=158k
R8 R16 R17: library part CMP-0020510-3, "RES, 2.0 k, 5%, 0.125 W, AEC-Q200 Grade 0, 0805", Manufacturer=Vishay-Dale, Power_W=125mW, Supplier Part Number 1=541-2.0KACT-ND, TempCo="200 ppm/C", Tolerance_%=5%, Value2=0.125W, Value_Code=2k00, ValueDisplayed=2.0k
R9 R15: library part CMP-0018610-3, "RES, 1.0 M, 5%, 0.25 W, AEC-Q200 Grade 0, 1206", Manufacturer=Vishay-Dale, Power_W=250mW, Supplier Part Number 1=541-1.0MECT-ND, TempCo="200 ppm/C", Tolerance_%=5%, Value2=0.25W, Value_Code=1M00, ValueDisplayed=1.0M
R10 R12 R18: library part CMP-0016911-3, "RES, 332 k, 1%, 0.25 W, AEC-Q200 Grade 0, 1206", Manufacturer=Vishay-Dale, Power_W=250mW, Supplier Part Number 1=541-332KFCT-ND, TempCo="100 ppm/C", Tolerance_%=1%, Value2=0.25W, Value_Code=332k
R11 R21: library part CMP-0020480-3, "RES, 1.0 M, 5%, 0.125 W, AEC-Q200 Grade 0, 0805", Manufacturer=Vishay-Dale, Power_W=125mW, Supplier Part Number 1=541-1.0MACT-ND, TempCo="200 ppm/C", Tolerance_%=5%, Value2=0.125W, Value_Code=1M00, ValueDisplayed=1.0M
R13: library part CMP-0022558-4, "RES, 6.04 k, 1%, 0.1 W, AEC-Q200 Grade 0, 0603", Manufacturer=Vishay-Dale, Power_W=100mW, Supplier Part Number 1=541-6.04KHCT-ND, TempCo="100 ppm/C", Tolerance_%=1%, Value2=0.1W, Value_Code=6k04, ValueDisplayed=6.04k
R14: library part CMP-0022109-5, "RES, 1.00 k, 1%, 0.1 W, AEC-Q200 Grade 0, 0603", Manufacturer=Vishay-Dale, Power_W=100mW, Supplier Part Number 1=541-1.00KHCT-ND, TempCo="100 ppm/C", Tolerance_%=1%, Value2=0.1W, Value_Code=1k00, ValueDisplayed=1.00k
R19 R22: library part CMP-0020566-3, "RES, 51 k, 5%, 0.125 W, AEC-Q200 Grade 0, 0805", Manufacturer=Vishay-Dale, Power_W=125mW, Supplier Part Number 1=541-51KACT-ND, TempCo="200 ppm/C", Tolerance_%=5%, Value2=0.125W, Value_Code=51k0, ValueDisplayed=51k
R20: library part CMP-0020559-3, "RES, 4.7 k, 5%, 0.125 W, AEC-Q200 Grade 0, 0805", Manufacturer=Vishay-Dale, Power_W=125mW, Supplier Part Number 1=541-4.7KACT-ND, TempCo="200 ppm/C", Tolerance_%=5%, Value2=0.125W, Value_Code=4k70, ValueDisplayed=4.7k
R23: library part CMP-0023530-3, "RES, 3.65 k, 0.1%, 0.1 W, 0603", Manufacturer="Susumu Co Ltd", Power_W=100mW, Supplier Part Number 1=RG16P3.65KBCT-ND, TempCo="25 ppm/C", Tolerance_%=0.1%, Value2=0.1W, Value_Code=3k65, ValueDisplayed=3.65k
R24: library part CMP-0022248-4, "RES, 26.1 k, 1%, 0.1 W, AEC-Q200 Grade 0, 0603", Manufacturer=Vishay-Dale, Power_W=100mW, Supplier Part Number 1=541-26.1KHCT-ND, TempCo="100 ppm/C", Tolerance_%=1%, Value2=0.1W, Value_Code=26k1, ValueDisplayed=26.1k
R26: library part CMP-0025768-4, "RES, 2.0 k, 5%, 0.1 W, AEC-Q200 Grade 0, 0603", Manufacturer=Vishay-Dale, Power_W=100mW, Supplier Part Number 1=541-2.0KGCT-ND, TempCo="200 ppm/C", Tolerance_%=5%, Value2=0.1W, Value_Code=2k00, ValueDisplayed=2.0k
R27: library part CMP-0025758-4, "RES, 22, 5%, 0.1 W, AEC-Q200 Grade 0, 0603", Manufacturer=Vishay-Dale, Power_W=100mW, Supplier Part Number 1=541-22GCT-ND, TempCo="200 ppm/C", Tolerance_%=5%, Value2=0.1W, Value_Code=22R0, ValueDisplayed=22
T1: "Transformer, Flyback, EFD30, Np:Ns = 1:6", Alternate Manufacturer=-, Manufacturer=Pulse
TP1 TP2 TP3 TP4: library part CMP-0055162-1, "Test Point, Miniature, SMT", Manufacturer=Keystone, PartNumber=5019, Supplier Part Number 1=36-5019TR-ND
TP5 TP6 TP7 TP8: library part CMP-0055152-1, "Test Point, Miniature, SMT", Manufacturer=Keystone, PartNumber=5015, Supplier Part Number 1=36-5015TR-ND
U1: library part CMP-0076391-1, "2.2MHz 60-V Low Side Controller for Boost, SEPIC and Flyback, DGS0010A (VSSOP-10)", Alternate Manufacturer="Texas Instruments", Alternate PartNumber=LM5022QDGSTQ1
